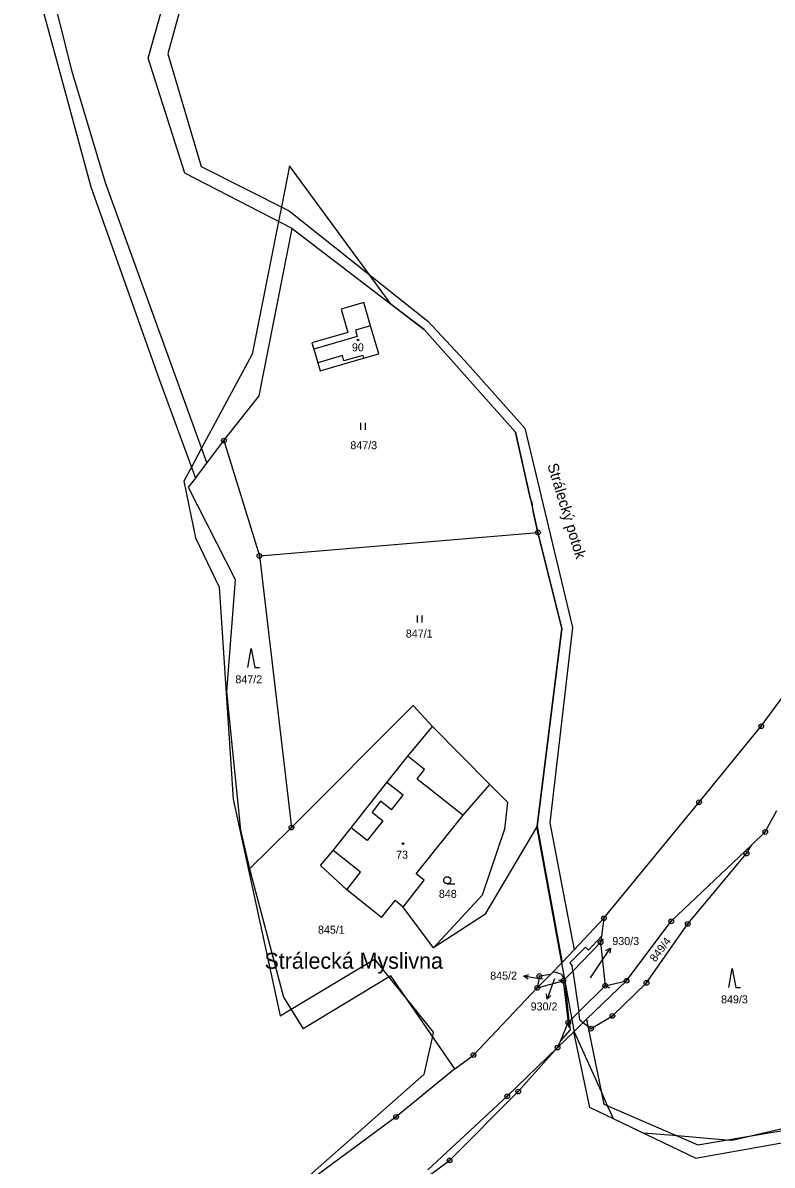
# Model space of a CAD drawing. Extents: x -547623 to -538651, y -1096714 to -1086522.
# Drawn here: x -543402.7 to -543243.5, y -1088531.7 to -1088289.2 of the extents above; entities that cross this region are included whole.
import ezdxf

# ---------------------------------------------------------------- set-up
doc = ezdxf.new("R2010")
doc.units = 0
for name, color, linetype in [('podzemní_provozovana', 7, 'Continuous'), ('Vrstva 1', 7, 'Continuous'), ('Vrstva 25', 7, 'Continuous'), ('Vrstva 33', 7, 'Continuous'), ('Vrstva 40', 7, 'Continuous'), ('Vrstva 50', 7, 'Continuous'), ('Vrstva 52', 7, 'Continuous'), ('Vrstva 62', 7, 'Continuous'), ('Vrstva 83', 7, 'Continuous'), ('Vrstva 86', 7, 'Continuous'), ('Vrstva 90', 7, 'Continuous'), ('Vrstva 92', 7, 'Continuous')]:
    doc.layers.add(name, color=color, linetype=linetype)

msp = doc.modelspace()

# ---------------------------------------------------------------- linework, layer by layer
at = {"layer": 'podzemní_provozovana'}
for p, q in [((-543279.51, -1088488.11), (-543277.84, -1088485.62)), ((-543293.3, -1088492.07), (-543296.26, -1088491.6)), ((-543290.26, -1088493.65), (-543291.28, -1088496.47))]:
    msp.add_line(p, q, dxfattribs=at)
for points in [[(-543278.81, -1088486.17), (-543277.84, -1088485.62), (-543277.98, -1088486.73)], [(-543282.07, -1088491.93), (-543279.51, -1088488.11)], [(-543295.35, -1088492.25), (-543296.26, -1088491.6), (-543295.2, -1088491.26)], [(-543292.3, -1088492.22), (-543293.3, -1088492.07)], [(-543289.73, -1088492.18), (-543290.26, -1088493.65)], [(-543290.47, -1088495.7), (-543291.28, -1088496.47), (-543291.41, -1088495.36)]]:
    msp.add_lwpolyline(points, dxfattribs=at)
at = {"layer": 'Vrstva 1'}
for p, q in [((-543244.93, -1088460.98), (-543242.5, -1088456.41)), ((-543247.78, -1088463.69), (-543244.93, -1088460.98)), ((-543264.91, -1088479.95), (-543247.78, -1088463.69)), ((-543248.92, -1088465.56), (-543247.78, -1088463.69)), ((-543261.4, -1088480.51), (-543248.92, -1088465.56)), ((-543279.22, -1088479.3), (-543279.74, -1088483.08)), ((-543270.17, -1088493.01), (-543261.4, -1088480.51)), ((-543279.74, -1088483.08), (-543282.47, -1088486.07)), ((-543279.74, -1088483.08), (-543279.92, -1088484.43)), ((-543283.11, -1088485.44), (-543286.47, -1088488.77)), ((-543282.47, -1088486.07), (-543283.11, -1088485.44)), ((-543288.08, -1088488.66), (-543290.58, -1088491.22)), ((-543289.9, -1088490.69), (-543290.58, -1088491.22)), ((-543288.33, -1088491.17), (-543289.9, -1088490.69)), ((-543286.47, -1088488.77), (-543285.99, -1088489.41)), ((-543285.83, -1088490.5), (-543285.99, -1088489.41)), ((-543285.83, -1088490.5), (-543284.56, -1088499.19)), ((-543290.58, -1088491.22), (-543293.37, -1088494.09)), ((-543292.91, -1088491.56), (-543293.37, -1088494.09)), ((-543290.58, -1088491.22), (-543292.91, -1088491.56)), ((-543288.33, -1088491.17), (-543287.61, -1088492.33)), ((-543287.42, -1088492.64), (-543287.61, -1088492.33)), ((-543286.58, -1088501.19), (-543287.42, -1088492.64)), ((-543277.42, -1088500.03), (-543270.17, -1088493.01)), ((-543284.31, -1088500.88), (-543284.56, -1088499.19)), ((-543282.91, -1088500.73), (-543282.61, -1088502.22)), ((-543281.95, -1088502.74), (-543277.42, -1088500.03)), ((-543288.48, -1088505.37), (-543286.79, -1088501.4)), ((-543288.48, -1088505.37), (-543286.4, -1088503.05)), ((-543286.58, -1088501.19), (-543286.4, -1088503.05)), ((-543284.31, -1088500.88), (-543283.62, -1088501.42)), ((-543283.62, -1088501.42), (-543282.61, -1088502.22)), ((-543282.61, -1088502.22), (-543279.23, -1088518.78)), ((-543282.61, -1088502.22), (-543281.95, -1088502.74)), ((-543289.08, -1088506.77), (-543288.48, -1088505.37)), ((-543297.42, -1088516.1), (-543289.08, -1088506.77)), ((-543312.01, -1088530.71), (-543297.42, -1088516.1)), ((-543356.14, -1088562.91), (-543312.01, -1088530.71))]:
    msp.add_line(p, q, dxfattribs=at)
for points in [[(-543360.21, -1088253.06), (-543371.91, -1088295.76)], [(-543376.04, -1088296.67), (-543364.11, -1088254.1)], [(-543399.81, -1088269.65), (-543392.38, -1088299.2)], [(-543402.7, -1088270.73), (-543395.76, -1088296.31)], [(-543395.76, -1088296.31), (-543388.26, -1088323.96)], [(-543368.25, -1088321.11), (-543376.04, -1088296.67)], [(-543371.91, -1088295.76), (-543364.77, -1088319.63)], [(-543392.38, -1088299.2), (-543385.18, -1088323.07)], [(-543345.47, -1088332.86), (-543368.25, -1088321.11)], [(-543364.77, -1088319.63), (-543346.13, -1088329.07)], [(-543385.18, -1088323.07), (-543363.58, -1088382.67)], [(-543388.26, -1088323.96), (-543373.65, -1088365.03)], [(-543346.13, -1088329.07), (-543316.63, -1088352.51)], [(-543352.51, -1088368.34), (-543345.47, -1088332.86)], [(-543345.47, -1088332.86), (-543317.45, -1088354.31)], [(-543330.23, -1088348.56), (-543335.07, -1088349.97)], [(-543335.07, -1088349.97), (-543333.63, -1088354.91)], [(-543328.79, -1088353.5), (-543330.23, -1088348.56)], [(-543316.63, -1088352.51), (-543308.74, -1088360.96)], [(-543333.63, -1088354.91), (-543341.26, -1088357.14)], [(-543327.06, -1088359.43), (-543328.79, -1088353.5)], [(-543317.45, -1088354.31), (-543298.04, -1088376.07)], [(-543341.26, -1088357.14), (-543340.87, -1088358.48)], [(-543340.87, -1088358.48), (-543340.03, -1088361.34)], [(-543330.29, -1088360.37), (-543327.06, -1088359.43)], [(-543340.03, -1088361.34), (-543339.53, -1088363.07)], [(-543339.53, -1088363.07), (-543330.29, -1088360.37)], [(-543308.74, -1088360.96), (-543296, -1088375.24)], [(-543373.65, -1088365.03), (-543366.02, -1088385.83)], [(-543359.96, -1088377.86), (-543352.51, -1088368.34)], [(-543298.04, -1088376.07), (-543293.23, -1088397.37)], [(-543296, -1088375.24), (-543285.9, -1088417.58)], [(-543363.58, -1088382.67), (-543359.96, -1088377.86)], [(-543359.96, -1088377.86), (-543352.42, -1088402.36)], [(-543366.02, -1088385.83), (-543363.58, -1088382.67)], [(-543366.02, -1088385.83), (-543367.57, -1088387.75)], [(-543367.57, -1088387.75), (-543357.56, -1088407.38)], [(-543352.42, -1088402.36), (-543293.23, -1088397.37)], [(-543293.23, -1088397.37), (-543288.13, -1088417.74)], [(-543352.42, -1088402.36), (-543345.63, -1088460.04)], [(-543357.56, -1088407.38), (-543359.4, -1088431.23)], [(-543288.13, -1088417.74), (-543293.42, -1088459.73)], [(-543285.9, -1088417.58), (-543290.74, -1088459.02)], [(-543245.78, -1088438.52), (-543237.46, -1088427.15)], [(-543359.4, -1088431.23), (-543356.43, -1088460.58)], [(-543345.63, -1088460.04), (-543319.75, -1088434.15)], [(-543319.75, -1088434.15), (-543315.67, -1088438.61)], [(-543320.91, -1088444.85), (-543315.67, -1088438.61)], [(-543315.67, -1088438.61), (-543303.45, -1088450.89)], [(-543258.98, -1088454.66), (-543245.78, -1088438.52)], [(-543325.32, -1088450.44), (-543320.91, -1088444.85)], [(-543332.96, -1088460.1), (-543325.32, -1088450.44)], [(-543309.16, -1088457.38), (-543303.45, -1088450.89)], [(-543303.45, -1088450.89), (-543299.74, -1088454.66)], [(-543299.74, -1088454.66), (-543300.37, -1088460.35)], [(-543279.22, -1088479.3), (-543258.98, -1088454.66)], [(-543319.11, -1088469.88), (-543309.16, -1088457.38)], [(-543290.74, -1088459.02), (-543285.54, -1088485.98)], [(-543356.43, -1088460.58), (-543354.53, -1088468.77)], [(-543345.63, -1088460.04), (-543354.53, -1088468.77)], [(-543336.74, -1088464.89), (-543332.96, -1088460.1)], [(-543300.37, -1088460.35), (-543305.12, -1088474.41)], [(-543293.42, -1088459.73), (-543304.54, -1088478.47)], [(-543293.42, -1088459.73), (-543288.08, -1088488.66)], [(-543339.46, -1088468.09), (-543336.74, -1088464.89)], [(-543354.53, -1088468.77), (-543347.28, -1088496.03)], [(-543333.88, -1088473.24), (-543339.46, -1088468.09)], [(-543321.87, -1088476.91), (-543317.39, -1088471.24)], [(-543317.39, -1088471.24), (-543319.11, -1088469.88)], [(-543326.46, -1088479.11), (-543333.88, -1088473.24)], [(-543326.46, -1088479.11), (-543323.61, -1088475.53)], [(-543321.87, -1088476.91), (-543323.61, -1088475.53)], [(-543315.45, -1088485.6), (-543305.12, -1088474.41)], [(-543315.45, -1088485.6), (-543321.87, -1088476.91)], [(-543304.54, -1088478.47), (-543315.45, -1088485.6)], [(-543285.54, -1088485.98), (-543279.22, -1088479.3)], [(-543274.39, -1088492.56), (-543264.91, -1088479.95)], [(-543279.92, -1088484.43), (-543278.93, -1088493.63)], [(-543324.51, -1088491.53), (-543343.12, -1088502.77)], [(-543310.89, -1088511.26), (-543324.51, -1088491.53)], [(-543293.37, -1088494.09), (-543287.85, -1088492.57)], [(-543287.85, -1088492.57), (-543286.79, -1088501.4)], [(-543282.91, -1088500.73), (-543274.39, -1088492.56)], [(-543278.93, -1088493.63), (-543274.39, -1088492.56)], [(-543306.96, -1088508.36), (-543293.37, -1088494.09)], [(-543347.28, -1088496.03), (-543343.12, -1088502.77)], [(-543289.08, -1088506.77), (-543285.64, -1088503.4)], [(-543282.24, -1088519.49), (-543285.64, -1088503.4)], [(-543289.08, -1088506.77), (-543299.75, -1088517.1)], [(-543310.89, -1088511.26), (-543306.96, -1088508.36)], [(-543310.89, -1088511.26), (-543323.38, -1088521.48)], [(-543299.75, -1088517.1), (-543316.67, -1088532.74)], [(-543259.76, -1088530.23), (-543282.24, -1088519.49)], [(-543279.23, -1088518.78), (-543259.29, -1088527.4)], [(-543323.38, -1088521.48), (-543343.15, -1088536.04)], [(-543259.29, -1088527.4), (-543222.35, -1088521.16)], [(-543259.76, -1088530.23), (-543221.5, -1088523.44)]]:
    msp.add_lwpolyline(points, dxfattribs=at)
at = {"layer": 'Vrstva 25'}
for p, q in [((-543330.89, -1088375.59), (-543330.89, -1088374.09)), ((-543329.89, -1088375.59), (-543329.89, -1088374.09)), ((-543318.84, -1088416.52), (-543318.84, -1088415.02)), ((-543317.84, -1088416.52), (-543317.84, -1088415.02)), ((-543312.52, -1088471.97), (-543310.92, -1088471.97))]:
    msp.add_line(p, q, dxfattribs=at)
for points in [[(-543354.9, -1088426.05), (-543354.2, -1088422.05), (-543353.4, -1088426.05), (-543352.4, -1088426.05)], [(-543252.67, -1088494), (-543251.97, -1088490), (-543251.17, -1088494), (-543250.17, -1088494)]]:
    msp.add_lwpolyline(points, dxfattribs=at)
for centre, radius in [((-543331.46, -1088356.5), 0.175), ((-543321.93, -1088463.43), 0.175), ((-543312.52, -1088471.22), 0.75)]:
    msp.add_circle(centre, radius, dxfattribs=at)
at = {"layer": 'Vrstva 33'}
for p, q in [((-543285.83, -1088490.5), (-543279.92, -1088484.43)), ((-543287.61, -1088492.33), (-543285.83, -1088490.5)), ((-543287.85, -1088492.57), (-543287.61, -1088492.33)), ((-543284.56, -1088499.19), (-543278.93, -1088493.63)), ((-543286.58, -1088501.19), (-543284.56, -1088499.19)), ((-543283.62, -1088501.42), (-543282.91, -1088500.73)), ((-543286.79, -1088501.4), (-543286.58, -1088501.19)), ((-543285.64, -1088503.4), (-543283.62, -1088501.42))]:
    msp.add_line(p, q, dxfattribs=at)
for points in [[(-543328.79, -1088353.5), (-543332.02, -1088354.45)], [(-543332.02, -1088354.45), (-543331.63, -1088355.78)], [(-543331.63, -1088355.78), (-543340.87, -1088358.48)], [(-543334.79, -1088359.81), (-543340.03, -1088361.34)], [(-543334.46, -1088360.95), (-543334.79, -1088359.81)], [(-543330.46, -1088359.78), (-543334.46, -1088360.95)], [(-543330.46, -1088359.78), (-543330.29, -1088360.37)], [(-543317.32, -1088447.69), (-543320.91, -1088444.85)], [(-543318.89, -1088449.69), (-543317.32, -1088447.69)], [(-543318.89, -1088449.69), (-543316.66, -1088451.45)], [(-543321.89, -1088453.15), (-543325.32, -1088450.44)], [(-543316.66, -1088451.45), (-543309.16, -1088457.38)], [(-543326.67, -1088454.44), (-543328.5, -1088456.75)], [(-543324.35, -1088456.27), (-543326.67, -1088454.44)], [(-543324.35, -1088456.27), (-543321.89, -1088453.15)], [(-543328.5, -1088456.75), (-543326.18, -1088458.58)], [(-543326.18, -1088458.58), (-543329.53, -1088462.81)], [(-543329.53, -1088462.81), (-543332.96, -1088460.1)], [(-543330.92, -1088469.49), (-543336.74, -1088464.89)], [(-543333.88, -1088473.24), (-543330.92, -1088469.49)], [(-543288.08, -1088488.66), (-543285.54, -1088485.98)]]:
    msp.add_lwpolyline(points, dxfattribs=at)
at = {"layer": 'Vrstva 40'}
for p, q in [((-543279.92, -1088484.43), (-543279.3, -1088483.64)), ((-543287.85, -1088492.57), (-543288.84, -1088492.42)), ((-543278.93, -1088493.63), (-543278.04, -1088494.08)), ((-543286.79, -1088501.4), (-543286.77, -1088502.4))]:
    msp.add_line(p, q, dxfattribs=at)
at = {"layer": 'Vrstva 52'}
for points in [[(-543293.45, -1088459.78), (-543293.42, -1088459.73), (-543288.13, -1088417.74), (-543293.23, -1088397.37), (-543294.23, -1088392.94), (-543294.5, -1088391), (-543294.82, -1088390.32), (-543298.04, -1088376.07), (-543317.45, -1088354.31), (-543324.4, -1088348.99), (-543329.05, -1088342.64), (-543346, -1088319.5), (-543347.75, -1088328.25), (-543348.37, -1088331.36), (-543354, -1088359.5), (-543364.73, -1088379.49), (-543366.88, -1088383.48), (-543368.5, -1088386.5), (-543366, -1088398.5), (-543361, -1088409), (-543358, -1088454), (-543348, -1088500), (-543345.69, -1088498.61), (-543328, -1088488), (-543324.94, -1088491.79), (-543320.69, -1088497.07), (-543315.5, -1088503.5), (-543315.68, -1088504.32), (-543317.5, -1088512.5), (-543343, -1088535)], [(-543217.61, -1088521.6), (-543222.52, -1088520.37), (-543224, -1088520), (-543246.76, -1088525.28), (-543252, -1088526.5), (-543253.31, -1088526.39), (-543263.61, -1088525.53), (-543270.86, -1088524.93), (-543277.17, -1088521.91), (-543278.43, -1088519.13), (-543279.76, -1088516.19), (-543285.5, -1088503.5), (-543288.18, -1088488.76), (-543293.45, -1088459.78)]]:
    msp.add_lwpolyline(points, dxfattribs=at)
at = {"layer": 'Vrstva 83'}
for centre, radius in [((-543359.96, -1088377.86), 0.5), ((-543359.96, -1088377.86), 0.1), ((-543293.23, -1088397.37), 0.5), ((-543293.23, -1088397.37), 0.1), ((-543352.42, -1088402.36), 0.5), ((-543352.42, -1088402.36), 0.1), ((-543245.78, -1088438.52), 0.5), ((-543245.78, -1088438.52), 0.1), ((-543258.98, -1088454.66), 0.5), ((-543258.98, -1088454.66), 0.1), ((-543345.63, -1088460.04), 0.5), ((-543345.63, -1088460.04), 0.1), ((-543244.93, -1088460.98), 0.5), ((-543244.93, -1088460.98), 0.1), ((-543248.92, -1088465.56), 0.5), ((-543248.92, -1088465.56), 0.1), ((-543279.22, -1088479.3), 0.5), ((-543279.22, -1088479.3), 0.1), ((-543264.91, -1088479.95), 0.5), ((-543264.91, -1088479.95), 0.1), ((-543261.4, -1088480.51), 0.5), ((-543261.4, -1088480.51), 0.1), ((-543279.92, -1088484.43), 0.5), ((-543279.92, -1088484.43), 0.1), ((-543292.91, -1088491.56), 0.5), ((-543292.91, -1088491.56), 0.1), ((-543287.85, -1088492.57), 0.5), ((-543287.85, -1088492.57), 0.1), ((-543278.93, -1088493.63), 0.5), ((-543274.39, -1088492.56), 0.5), ((-543274.39, -1088492.56), 0.1), ((-543270.17, -1088493.01), 0.5), ((-543270.17, -1088493.01), 0.1), ((-543293.37, -1088494.09), 0.5), ((-543293.37, -1088494.09), 0.1), ((-543278.93, -1088493.63), 0.1), ((-543277.42, -1088500.03), 0.5), ((-543277.42, -1088500.03), 0.1), ((-543286.79, -1088501.4), 0.5), ((-543286.79, -1088501.4), 0.1), ((-543281.95, -1088502.74), 0.5), ((-543281.95, -1088502.74), 0.1), ((-543306.96, -1088508.36), 0.5), ((-543289.08, -1088506.77), 0.5), ((-543289.08, -1088506.77), 0.1), ((-543306.96, -1088508.36), 0.1), ((-543299.75, -1088517.1), 0.5), ((-543299.75, -1088517.1), 0.1), ((-543297.42, -1088516.1), 0.5), ((-543297.42, -1088516.1), 0.1), ((-543323.38, -1088521.48), 0.5), ((-543323.38, -1088521.48), 0.1), ((-543312.01, -1088530.71), 0.5), ((-543312.01, -1088530.71), 0.1)]:
    msp.add_circle(centre, radius, dxfattribs=at)
at = {"layer": 'Vrstva 90'}
for points in [[(-543328.79, -1088353.5), (-543332.02, -1088354.45)], [(-543332.02, -1088354.45), (-543331.63, -1088355.78)], [(-543327.06, -1088359.43), (-543328.79, -1088353.5)], [(-543331.63, -1088355.78), (-543340.87, -1088358.48)], [(-543340.87, -1088358.48), (-543340.03, -1088361.34)], [(-543334.79, -1088359.81), (-543340.03, -1088361.34)], [(-543334.46, -1088360.95), (-543334.79, -1088359.81)], [(-543330.46, -1088359.78), (-543334.46, -1088360.95)], [(-543330.46, -1088359.78), (-543330.29, -1088360.37)], [(-543330.29, -1088360.37), (-543327.06, -1088359.43)], [(-543325.32, -1088450.44), (-543320.91, -1088444.85)], [(-543317.32, -1088447.69), (-543320.91, -1088444.85)], [(-543318.89, -1088449.69), (-543317.32, -1088447.69)], [(-543318.89, -1088449.69), (-543316.66, -1088451.45)], [(-543321.89, -1088453.15), (-543325.32, -1088450.44)], [(-543316.66, -1088451.45), (-543309.16, -1088457.38)], [(-543326.67, -1088454.44), (-543328.5, -1088456.75)], [(-543324.35, -1088456.27), (-543326.67, -1088454.44)], [(-543324.35, -1088456.27), (-543321.89, -1088453.15)], [(-543328.5, -1088456.75), (-543326.18, -1088458.58)], [(-543326.18, -1088458.58), (-543329.53, -1088462.81)], [(-543319.11, -1088469.88), (-543309.16, -1088457.38)], [(-543336.74, -1088464.89), (-543332.96, -1088460.1)], [(-543329.53, -1088462.81), (-543332.96, -1088460.1)], [(-543330.92, -1088469.49), (-543336.74, -1088464.89)], [(-543333.88, -1088473.24), (-543330.92, -1088469.49)], [(-543321.87, -1088476.91), (-543317.39, -1088471.24)], [(-543317.39, -1088471.24), (-543319.11, -1088469.88)], [(-543326.46, -1088479.11), (-543333.88, -1088473.24)], [(-543326.46, -1088479.11), (-543323.61, -1088475.53)], [(-543321.87, -1088476.91), (-543323.61, -1088475.53)]]:
    msp.add_lwpolyline(points, dxfattribs=at)

# ---------------------------------------------------------------- texts
at = {"layer": 'podzemní_provozovana'}
for s, p in [('930/3', (-543277.43, -1088484.99)), ('845/2', (-543303.38, -1088492.33)), ('930/2', (-543294.78, -1088498.87))]:
    msp.add_text(s, height=1.7, dxfattribs=at).set_placement(p)
at = {"layer": 'Vrstva 50'}
msp.add_text('Strálecký potok', height=2.3, rotation=286.9966, dxfattribs=at).set_placement((-543291.27, -1088383.07))
at = {"layer": 'Vrstva 62'}
msp.add_text('Strálecká Myslivna', height=3.4, dxfattribs=at).set_placement((-543351.34, -1088490.02))
at = {"layer": 'Vrstva 86'}
for s, height, p in [('847/3', 1.7, (-543333.1, -1088379.7)), ('847/1', 1.7, (-543321.31, -1088419.7)), ('847/2', 1.7, (-543357.53, -1088429.41)), ('848', 1.7, (-543314.29, -1088474.96)), ('845/1', 1.7, (-543339.98, -1088482.58)), ('845/2', 0.1, (-543292.3, -1088492.22)), ('930/2', 0.1, (-543289.73, -1088492.18)), ('930/3', 0.1, (-543282.07, -1088491.93)), ('849/3', 1.7, (-543254.32, -1088497.36))]:
    msp.add_text(s, height=height, dxfattribs=at).set_placement(p)
msp.add_text('849/4', height=1.7, rotation=53.1, dxfattribs=at).set_placement((-543268.28, -1088488.71))
at = {"layer": 'Vrstva 92'}
for s, p in [('90', (-543332.76, -1088358.91)), ('73', (-543323.38, -1088466.65))]:
    msp.add_text(s, height=1.7, dxfattribs=at).set_placement(p)

doc.saveas('drawing.dxf')
